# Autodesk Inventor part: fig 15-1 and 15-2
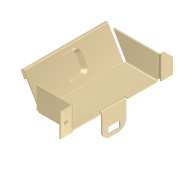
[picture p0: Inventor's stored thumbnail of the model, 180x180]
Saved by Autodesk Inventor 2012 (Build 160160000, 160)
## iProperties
Shininess: 65.0
Angle Display Precision: 2
Document Length Units: 11269
Document Angle Units: 11279
Document Time Units: 11290
Document Mass Units: 11283
Document Length Units Precision: 3
Document Angle Units Precision: 2
Compacted: False
Created: 2002-04
Part Number: fig 15-1 and 15-2
Material: Stainless Steel, 440C
Document SubType Name: Sheet Metal
Density: 1 g/cm^3
Sheet Metal Rule: Default
Density: 0.0
Volumn: 0.0
Area: 0.0
PropertySet Name: Model Information
Control State: 0
Master: False
Checked Out: False
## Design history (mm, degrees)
node "Face1"
  sketch "Sketch1"
    geometry: L1 (-46.618, 22.343)-(-46.618, -12.657); L2 (-46.618, -12.657)-(53.382, -12.657); L3 (53.382, -12.657)-(53.382, 22.343); L4 (53.382, 22.343)-(35.882, 22.343); L5 (35.882, 22.343)-(35.882, 12.343); L6 (35.882, 12.343)-(-29.118, 12.343); L7 (-29.118, 12.343)-(-29.118, 22.343); L8 (-29.118, 22.343)-(-46.618, 22.343)
    constraints: 16 end point, 6 parallel, 2 equal length, 1 perpendicular, 1 vertical
    dimensions: "d0" = 100 distance of L1.end L2.end; "d1" = 35 distance of L1.start L1.end; "d2" = 65 distance of L5.end L6.end; "d3" = 10 distance of L6.end L7.end
sketch "Sketch2"
  geometry: L1 (100, 0)-(0, 0) reference; L2 (17.5, 35)-(17.5, 25) reference; L3 (17.5, 25)-(17.5, 0); L4 (82.5, 25)-(82.5, 0)
  constraints: 4 end point, 2 point on line, 1 collinear, 1 perpendicular
feature "Fold1" dims "d5" = 1 (= BendRadius), "d6" = 90 deg, "d7" = 1 (= BendRadius), "d52" = 1 (= BendReliefWidth), "d53" = 0.5 (= BendReliefDepth), "d54" = 2 (= MinimumRemnant), "SeamGap" = 0.01, "Thickness" = 1
feature "Fold2" dims "d8" = 1 (= BendRadius), "d9" = 90 deg, "d10" = 1 (= BendRadius), "d55" = 1 (= BendReliefWidth), "d56" = 0.5 (= BendReliefDepth), "d57" = 2 (= MinimumRemnant), "SeamGap" = 0.01, "Thickness" = 1
node "Flange1"
feature "Corner1" dims "d15" = 1 (= Thickness), "d16" = 0, "d73" = 4 (= CornerReliefSize), "Thickness" = 1, "TransitionRadius" = 1 (= BendRadius)
sketch "Sketch4"
  geometry: L1 (0, 0)-(0, 35) reference; L2 (15.869, 25)-(15.869, 26) reference; L3 (17.5, 26)-(0, 26)
  constraints: 2 end point, 1 perpendicular, 1 point on line
feature "Fold3" sketch "Sketch4" dims "d17" = 1 (= BendRadius), "d18" = 90 deg, "d19" = 1 (= BendRadius), "d61" = 1 (= BendReliefWidth), "d62" = 0.5 (= BendReliefDepth), "d63" = 2 (= MinimumRemnant), "SeamGap" = 0.01, "Thickness" = 1
sketch "Sketch5"
  geometry: L1 (-17.5, -34.296)-(-17.5, 9) reference; L2 (0, 0)-(-17.5, 0)
  constraints: 2 end point, 1 perpendicular, 1 point on line
feature "Fold4" sketch "Sketch5" dims "d20" = 1 (= BendRadius), "d21" = 90 deg, "d22" = 1 (= BendRadius), "d64" = 1 (= BendReliefWidth), "d65" = 0.5 (= BendReliefDepth), "d66" = 2 (= MinimumRemnant), "SeamGap" = 0.01, "Thickness" = 1
sketch "Sketch6"
  geometry: 1 further point
feature "iFeature4:1" sketch "Sketch6"
feature "Hem2" dims "d32" = 1 (= BendRadius), "d33" = 6 (= 6 x Thickness), "d34" = 1 (= Thickness), "d35" = 0.5 (= 0.5 x d34), "d67" = 1 (= BendReliefWidth), "d68" = 0.5 (= BendReliefDepth), "d69" = 2 (= MinimumRemnant), "SeamGap" = 0.01, "Thickness" = 1, "MinimumRemnant" = 2 (= 2 x Thickness), "BendReliefWidth" = 1 (= Thickness)
node "Face2"
  sketch "Sketch9"
    geometry: L1 (0, 0)-(62.738, 0) reference; L2 (40.511, 0)-(22.35, 0); L3 (22.35, 0)-(22.35, 18.987); L4 (22.35, 18.987)-(40.511, 18.987); L5 (40.511, 18.987)-(40.511, 0)
    constraints: 8 end point, 2 parallel, 1 horizontal, 1 perpendicular, 1 point on line
sketch "Sketch10"
  geometry: L1 (13.661, -2.202)-(4.661, -2.202); L2 (4.661, -2.202)-(4.661, -7.127); L3 (4.661, -7.127)-(13.661, -7.127); L4 (13.661, -7.127)-(13.661, -2.202); L5 (18.161, -16.987)-(18.161, 0) reference
  constraints: 8 end point, 2 parallel, 1 horizontal, 1 perpendicular
  dimensions: "d50" = 4.5 distance between parallel lines of L5 L4; "d51" = 9 distance of L1.start L1.end
cut "Cut1" sketch "Sketch10" dims "d38" = 1 (= Thickness), "d39" = 0
sketch "Sketch11"
  geometry: 1 further point
hole "Hole1" sketch "Sketch11" at (3.935, 8.75) diameter "d40" = 3; stored, may be unused: countersink angle "d44" = 82 deg, drill point angle "d46" = 118 deg; dims "d41" = 6, "d42" = 4, "d43" = 2, "d45" = 8
feature "Corner Chamfer1" dims "d47" = 6, "d48" = 6, angle "d74" = 45 deg
feature "Corner Round1" dims "d49" = 6
body "Solid1"
face "Plate1" dims "Thickness" = 1
sketch "Sketch3"
  geometry: L1 (62.738, 0)-(62.738, -25); L2 (62.738, -25)-(0, -25); 2 other entities
  constraints: 4 end point, 4 other
face "Plate2" dims "d12" = 25, "d13" = 120 deg, "d14" = 1 (= BendRadius), "Thickness" = 1, "MinimumRemnant" = 2 (= 2 x Thickness), "BendReliefWidth" = 1 (= Thickness)
bend "Bend1" dims "d11" = 1 (= BendRadius), "d12" = 25, "d13" = 120 deg, "d14" = 1 (= BendRadius), "d58" = 1 (= BendReliefWidth), "d59" = 0.5 (= BendReliefDepth), "d60" = 2 (= MinimumRemnant), "SeamGap" = 0.01, "Thickness" = 1, "MinimumRemnant" = 2 (= 2 x Thickness), "BendReliefWidth" = 1 (= Thickness)
sketch "Sketch8"
  geometry: L1 (0.866, 0.5)-(0, 0); L2 (-0.866, -0.5)-(1.384, -4.397); L3 (1.384, -4.397)-(0.518, -4.897); L4 (0.518, -4.897)-(-1.732, -1); A1 r 0.5 centre (-0.433, -0.25) between (0, 0) and (-0.866, -0.5); A2 r 1.5 centre (-0.433, -0.25) between (0.866, 0.5) and (-1.732, -1)
  constraints: 8 end point, 4 point on circle
face "Plate3" dims "d36" = 1 (= BendRadius), "Thickness" = 1, "MinimumRemnant" = 2 (= 2 x Thickness), "BendReliefWidth" = 1 (= Thickness)
bend "Bend2" dims "d36" = 1 (= BendRadius), "d37" = 1 (= BendRadius), "d70" = 1 (= BendReliefWidth), "d71" = 0.5 (= BendReliefDepth), "d72" = 2 (= MinimumRemnant), "SeamGap" = 0.01, "Thickness" = 1, "MinimumRemnant" = 2 (= 2 x Thickness), "BendReliefWidth" = 1 (= Thickness)
other parameters: "BendRadius" = 1 (= Thickness), "BendReliefDepth" = 0.5 (= 0.5 x Thickness), "CornerReliefSize" = 4 (= 4 x Thickness), "d4" = 1 (= BendRadius), "d27" = 0, "JacobiRadiusSize" = 1 (= Thickness), "GapSize" = 1 (= Thickness)
